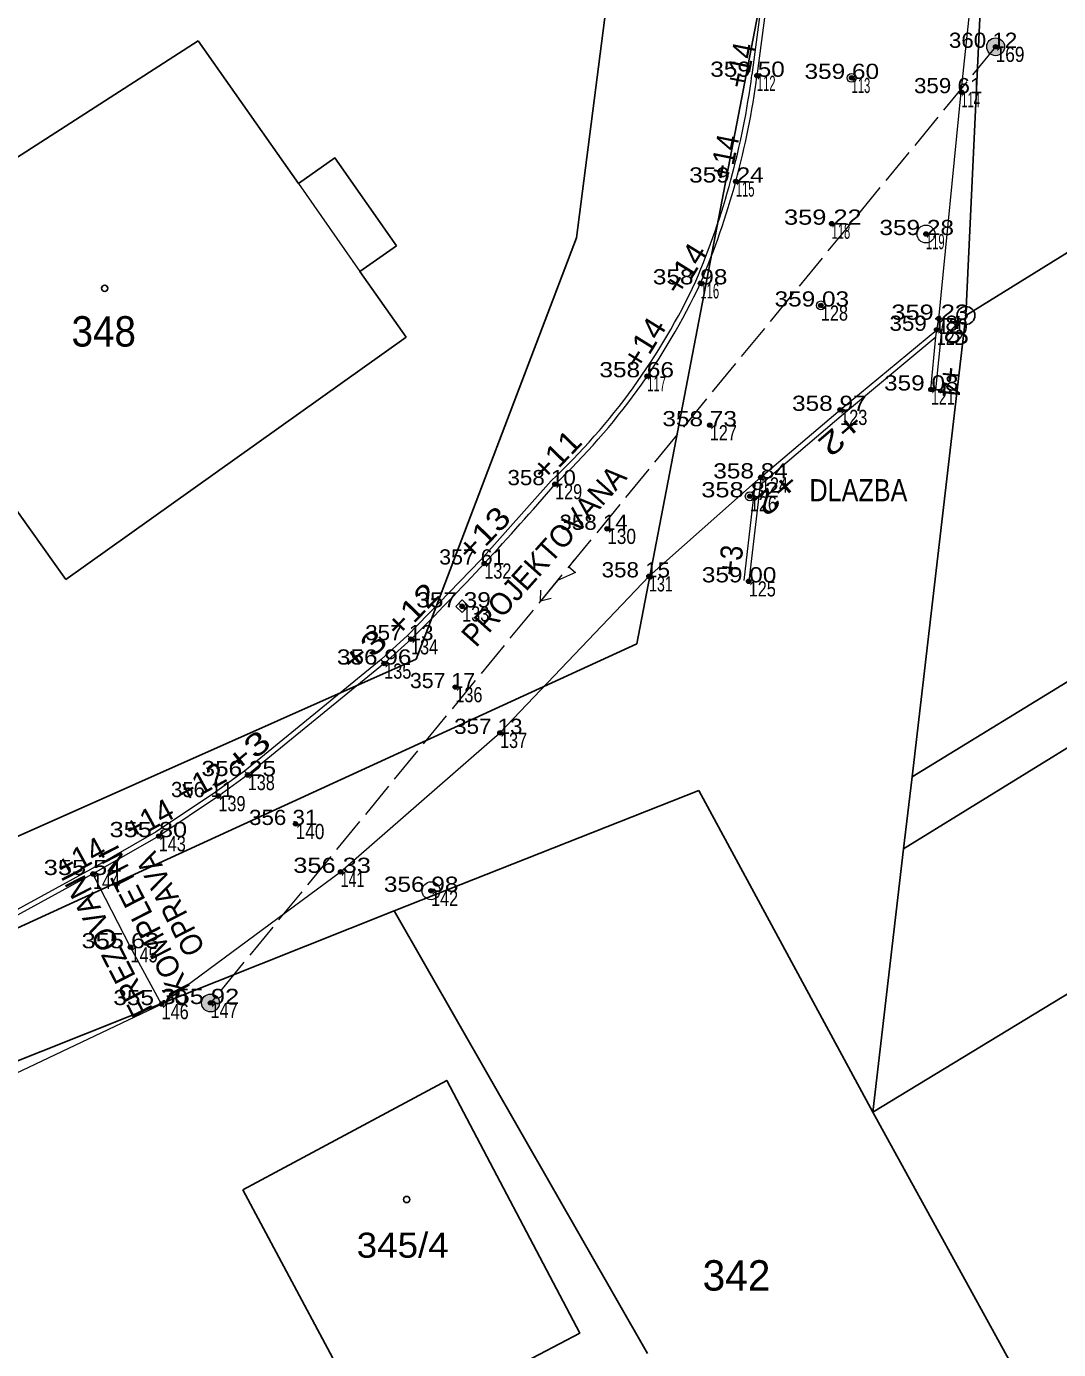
# Model space of a CAD drawing. Extents: x -592965 to -592390, y -1145071 to -1144631.
# Drawn here: x -592667.32 to -592638.44, y -1144937.57 to -1144900.54 of the extents above; entities that cross this region are included whole.
import ezdxf
from ezdxf.enums import TextEntityAlignment as Align

# ---------------------------------------------------------------- set-up
doc = ezdxf.new("R2010")
doc.units = 0
doc.header["$LTSCALE"] = 0.17
doc.header["$PDMODE"] = 32
doc.header["$PDSIZE"] = 0.085
doc.linetypes.add('LONG_DASHED', pattern=[7.5, 6, -1.5])
for name, color, linetype, lineweight in [('1', 7, 'Continuous', 13), ('3', 7, 'Continuous', 13), ('4', 7, 'Continuous', 25)]:
    doc.layers.add(name, color=color, linetype=linetype, lineweight=lineweight)
doc.layers.add('2', color=7, linetype='Continuous')

msp = doc.modelspace()

# ---------------------------------------------------------------- hatches: boundary and pattern name
at = {"layer": '1'}
for points in [[(-592639.95, -1144901.11, 1), (-592640.45, -1144901.11, 1)], [(-592661.92, -1144927.87, 1), (-592662.42, -1144927.87, 1)]]:
    msp.add_hatch(color=256, dxfattribs=at).paths.add_polyline_path(points)

# ---------------------------------------------------------------- linework, layer by layer
at = {"layer": '1', "linetype": 'LONG_DASHED'}
msp.add_line((-592640.2, -1144901.11), (-592662.17, -1144927.87), dxfattribs=at)
at = {"layer": '1'}
for p, q in [((-592641.85, -1144909.03), (-592641.79, -1144908.72)), ((-592646.93, -1144913.3), (-592647.25, -1144916.05)), ((-592655.041, -1144916.858), (-592655.219, -1144916.682)), ((-592656.56, -1144917.69), (-592656.66, -1144917.59)), ((-592657.31, -1144918.37), (-592657.4, -1144918.26)), ((-592661.13, -1144921.49), (-592661.22, -1144921.38)), ((-592661.95, -1144922.08), (-592662.03, -1144921.97))]:
    msp.add_line(p, q, dxfattribs=at)
for points in [[(-592641.79, -1144908.72), (-592641.16, -1144902.38), (-592640.38, -1144895.02), (-592640.15, -1144889.82), (-592640.65, -1144883.36), (-592641.29, -1144877.49), (-592642.3, -1144871.74), (-592643.21, -1144867.79), (-592644.53, -1144861.22), (-592645.89, -1144855.01), (-592647.22, -1144849.42), (-592648.49, -1144841.98), (-592649.04, -1144837.88), (-592648.65, -1144833.94), (-592647.63, -1144830.74), (-592645.94, -1144827.26), (-592642.72, -1144822.58), (-592638.67, -1144817.55), (-592634.67, -1144812.8), (-592632.14, -1144809.3), (-592630.54, -1144806.22), (-592629.58, -1144805.74)], [(-592647.47, -1144872.18), (-592646.45, -1144878.08), (-592646.19, -1144880.05), (-592646.12, -1144881.06), (-592646.02, -1144883.03), (-592645.98, -1144885.03), (-592645.96, -1144886.03), (-592645.96, -1144889.02), (-592646.04, -1144891.02), (-592646.42, -1144895.95), (-592646.76, -1144899.93), (-592647.02, -1144901.9)], [(-592647.33, -1144872.14), (-592646.31, -1144878.06), (-592646.05, -1144880.04), (-592645.98, -1144881.05), (-592645.88, -1144883.03), (-592645.84, -1144885.03), (-592645.82, -1144886.03), (-592645.82, -1144889.02), (-592645.9, -1144891.03), (-592646.28, -1144895.96), (-592646.62, -1144899.95), (-592646.88, -1144901.92)], [(-592646.77, -1144913.16), (-592644.55, -1144911.27), (-592641.85, -1144909.03)], [(-592642.01, -1144910.7), (-592641.87, -1144910.71), (-592641.71, -1144909.05), (-592641.65, -1144908.75), (-592641.79, -1144908.72)], [(-592642.01, -1144910.7), (-592641.87, -1144909.23), (-592641.85, -1144909.03)], [(-592646.79, -1144913.37), (-592644.46, -1144911.38), (-592641.87, -1144909.23)], [(-592652.64, -1144913.26), (-592654.61, -1144915.47), (-592656.66, -1144917.59), (-592657.4, -1144918.26), (-592661.22, -1144921.38), (-592662.03, -1144921.97), (-592663.69, -1144923.08), (-592665.53, -1144924.14), (-592669.78, -1144926.46), (-592671.54, -1144927.35), (-592674.79, -1144928.86), (-592677.96, -1144930.1), (-592680.85, -1144930.93), (-592682.8, -1144931.31), (-592683.28, -1144931.38)], [(-592682.22, -1144935.34), (-592678.43, -1144934.2), (-592676.64, -1144933.56), (-592669.86, -1144930.9), (-592663.54, -1144927.9), (-592658.53, -1144924.2), (-592654.07, -1144920.31), (-592649.9, -1144915.93), (-592646.93, -1144913.3), (-592646.77, -1144913.16)], [(-592646.77, -1144913.16), (-592646.79, -1144913.37), (-592647.11, -1144916.07)], [(-592651.99, -1144915.469), (-592652.148, -1144915.663), (-592651.955, -1144915.821), (-592652.465, -1144916.05), (-592652.94, -1144916.63)], [(-592652.637, -1144916.555), (-592652.94, -1144916.63), (-592652.927, -1144916.318)], [(-592656.56, -1144917.69), (-592657.31, -1144918.37), (-592661.13, -1144921.49), (-592661.95, -1144922.08), (-592663.62, -1144923.2), (-592665.46, -1144924.26), (-592669.71, -1144926.58), (-592671.48, -1144927.48), (-592674.74, -1144928.99), (-592677.92, -1144930.23), (-592680.82, -1144931.07), (-592682.78, -1144931.45), (-592683.26, -1144931.52)], [(-592663.54, -1144927.9), (-592664.41, -1144926.31), (-592665.46, -1144924.26)]]:
    msp.add_lwpolyline(points, dxfattribs=at)
msp.add_lwpolyline([(-592654.953, -1144916.768), (-592655.132, -1144916.593), (-592655.307, -1144916.772), (-592655.128, -1144916.947)], close=True, dxfattribs=at)
for centre, radius in [((-592640.2, -1144901.11), 0.25), ((-592644.23, -1144901.98), 0.125), ((-592642.15, -1144906.35), 0.25), ((-592645.09, -1144908.35), 0.125), ((-592647.08, -1144913.69), 0.125), ((-592656, -1144924.73), 0.25), ((-592662.17, -1144927.87), 0.25)]:
    msp.add_circle(centre, radius, dxfattribs=at)
for centre, radius, start, end in [((-592668.9952, -1144899.0192), 22.1632, 337.02545, 352.53154), ((-592668.6512, -1144899.1193), 21.9506, 336.9037, 352.66952), ((-592665.0908, -1144899.9771), 18.206, 313.14815, 335.00458), ((-592665.3788, -1144899.7612), 18.7015, 313.39658, 334.77936), ((-592708.3676, -1144865.5418), 73.5082, 314.81231, 319.42987)]:
    msp.add_arc(centre, radius, start, end, dxfattribs=at)
at = {"layer": '2'}
for p in [(-592640.2, -1144901.11), (-592646.88, -1144901.92), (-592644.23, -1144901.98), (-592641.16, -1144902.38), (-592647.47, -1144904.88), (-592644.79, -1144906.06), (-592642.15, -1144906.35), (-592648.46, -1144907.73), (-592645.09, -1144908.35), (-592641.79, -1144908.72), (-592641.85, -1144909.03), (-592649.95, -1144910.33), (-592642.01, -1144910.7), (-592644.55, -1144911.27), (-592648.2, -1144911.7), (-592646.77, -1144913.16), (-592652.53, -1144913.35), (-592647.08, -1144913.69), (-592651.07, -1144914.6), (-592654.51, -1144915.57), (-592649.9, -1144915.93), (-592647.11, -1144916.07), (-592655.13, -1144916.77), (-592656.56, -1144917.69), (-592657.31, -1144918.37), (-592655.32, -1144919.03), (-592654.07, -1144920.31), (-592661.13, -1144921.49), (-592661.95, -1144922.08), (-592659.79, -1144922.86), (-592663.62, -1144923.2), (-592665.46, -1144924.26), (-592658.53, -1144924.2), (-592656, -1144924.73), (-592664.41, -1144926.31), (-592663.54, -1144927.9), (-592662.17, -1144927.87)]:
    msp.add_point(p, dxfattribs=at)
at = {"layer": '3'}
for centre, radius in [((-592640.2001, -1144901.1099), 0.0625), ((-592640.2001, -1144901.1099), 0.0395), ((-592640.2001, -1144901.1099), 0.0125), ((-592646.8801, -1144901.9199), 0.0625), ((-592646.8801, -1144901.9199), 0.0395), ((-592646.8801, -1144901.9199), 0.0125), ((-592644.2301, -1144901.9799), 0.0625), ((-592644.2301, -1144901.9799), 0.0395), ((-592644.2301, -1144901.9799), 0.0125), ((-592641.1601, -1144902.3799), 0.0625), ((-592641.1601, -1144902.3799), 0.0395), ((-592641.1601, -1144902.3799), 0.0125), ((-592647.4701, -1144904.8799), 0.0625), ((-592647.4701, -1144904.8799), 0.0395), ((-592647.4701, -1144904.8799), 0.0125), ((-592644.7901, -1144906.0599), 0.0625), ((-592644.7901, -1144906.0599), 0.0395), ((-592644.7901, -1144906.0599), 0.0125), ((-592642.1501, -1144906.3499), 0.0625), ((-592642.1501, -1144906.3499), 0.0395), ((-592642.1501, -1144906.3499), 0.0125), ((-592648.4601, -1144907.7299), 0.0625), ((-592648.4601, -1144907.7299), 0.0395), ((-592648.4601, -1144907.7299), 0.0125), ((-592645.0901, -1144908.3499), 0.0625), ((-592645.0901, -1144908.3499), 0.0395), ((-592645.0901, -1144908.3499), 0.0125), ((-592641.7901, -1144908.7199), 0.0625), ((-592641.7901, -1144908.7199), 0.0395), ((-592641.8501, -1144909.0299), 0.0625), ((-592641.8501, -1144909.0299), 0.0395), ((-592641.8501, -1144909.0299), 0.0125), ((-592641.7901, -1144908.7199), 0.0125), ((-592649.9501, -1144910.3299), 0.0625), ((-592649.9501, -1144910.3299), 0.0395), ((-592649.9501, -1144910.3299), 0.0125), ((-592642.0101, -1144910.6999), 0.0625), ((-592642.0101, -1144910.6999), 0.0395), ((-592642.0101, -1144910.6999), 0.0125), ((-592644.5501, -1144911.2699), 0.0625), ((-592644.5501, -1144911.2699), 0.0395), ((-592644.5501, -1144911.2699), 0.0125), ((-592648.2001, -1144911.6999), 0.0625), ((-592648.2001, -1144911.6999), 0.0395), ((-592648.2001, -1144911.6999), 0.0125), ((-592646.7701, -1144913.1599), 0.0625), ((-592646.7701, -1144913.1599), 0.0395), ((-592646.7701, -1144913.1599), 0.0125), ((-592652.5301, -1144913.3499), 0.0625), ((-592652.5301, -1144913.3499), 0.0395), ((-592652.5301, -1144913.3499), 0.0125), ((-592647.0801, -1144913.6899), 0.0625), ((-592647.0801, -1144913.6899), 0.0395), ((-592647.0801, -1144913.6899), 0.0125), ((-592651.0701, -1144914.5999), 0.0625), ((-592651.0701, -1144914.5999), 0.0395), ((-592651.0701, -1144914.5999), 0.0125), ((-592654.5101, -1144915.5699), 0.0625), ((-592654.5101, -1144915.5699), 0.0395), ((-592654.5101, -1144915.5699), 0.0125), ((-592649.9001, -1144915.9299), 0.0625), ((-592649.9001, -1144915.9299), 0.0395), ((-592649.9001, -1144915.9299), 0.0125), ((-592647.1101, -1144916.0699), 0.0625), ((-592647.1101, -1144916.0699), 0.0395), ((-592647.1101, -1144916.0699), 0.0125), ((-592655.1301, -1144916.7699), 0.0625), ((-592655.1301, -1144916.7699), 0.0395), ((-592655.1301, -1144916.7699), 0.0125), ((-592656.5601, -1144917.6899), 0.0625), ((-592656.5601, -1144917.6899), 0.0395), ((-592656.5601, -1144917.6899), 0.0125), ((-592657.3101, -1144918.3699), 0.0625), ((-592657.3101, -1144918.3699), 0.0395), ((-592657.3101, -1144918.3699), 0.0125), ((-592655.3201, -1144919.0299), 0.0625), ((-592655.3201, -1144919.0299), 0.0395), ((-592655.3201, -1144919.0299), 0.0125), ((-592654.0701, -1144920.3099), 0.0625), ((-592654.0701, -1144920.3099), 0.0395), ((-592654.0701, -1144920.3099), 0.0125), ((-592661.1301, -1144921.4899), 0.0625), ((-592661.1301, -1144921.4899), 0.0395), ((-592661.1301, -1144921.4899), 0.0125), ((-592661.9501, -1144922.0799), 0.0625), ((-592661.9501, -1144922.0799), 0.0395), ((-592661.9501, -1144922.0799), 0.0125), ((-592663.6201, -1144923.1999), 0.0625), ((-592659.7901, -1144922.8599), 0.0625), ((-592659.7901, -1144922.8599), 0.0395), ((-592659.7901, -1144922.8599), 0.0125), ((-592663.6201, -1144923.1999), 0.0395), ((-592663.6201, -1144923.1999), 0.0125), ((-592665.4601, -1144924.2599), 0.0625), ((-592665.4601, -1144924.2599), 0.0395), ((-592665.4601, -1144924.2599), 0.0125), ((-592658.5301, -1144924.1999), 0.0625), ((-592658.5301, -1144924.1999), 0.0395), ((-592658.5301, -1144924.1999), 0.0125), ((-592656.0001, -1144924.7299), 0.0625), ((-592656.0001, -1144924.7299), 0.0395), ((-592656.0001, -1144924.7299), 0.0125), ((-592664.4101, -1144926.3099), 0.0625), ((-592664.4101, -1144926.3099), 0.0395), ((-592664.4101, -1144926.3099), 0.0125), ((-592663.5401, -1144927.8999), 0.0625), ((-592663.5401, -1144927.8999), 0.0395), ((-592663.5401, -1144927.8999), 0.0125), ((-592662.1701, -1144927.8699), 0.0625), ((-592662.1701, -1144927.8699), 0.0395), ((-592662.1701, -1144927.8699), 0.0125)]:
    msp.add_circle(centre, radius, dxfattribs=at)
at = {"layer": '4'}
for p, q in [((-592641.03, -1144908.63), (-592639.79, -1144882.02)), ((-592650.24, -1144917.82), (-592643.83, -1144884.47)), ((-592651.93, -1144906.46), (-592649.48, -1144887.5)), ((-592641.03, -1144908.63), (-592618.69, -1144894.73)), ((-592668.9, -1144905.05), (-592662.52, -1144900.94)), ((-592662.52, -1144900.94), (-592659.71, -1144904.94)), ((-592656.42, -1144918.25), (-592651.93, -1144906.46)), ((-592657.99, -1144907.4), (-592656.97, -1144906.68)), ((-592657.99, -1144907.4), (-592656.7, -1144909.24)), ((-592671.91, -1144908.03), (-592666.22, -1144916.02)), ((-592642.54, -1144921.54), (-592641.03, -1144908.63)), ((-592666.22, -1144916.02), (-592656.7, -1144909.24)), ((-592642.54, -1144921.54), (-592628.83, -1144913.14)), ((-592643.64, -1144930.93), (-592616.08, -1144914.18)), ((-592642.78, -1144923.56), (-592628, -1144914.45)), ((-592683.65, -1144933.15), (-592650.24, -1144917.82)), ((-592684.12, -1144930.55), (-592656.42, -1144918.25)), ((-592642.78, -1144923.56), (-592642.54, -1144921.54)), ((-592657.03, -1144925.29), (-592648.51, -1144921.92)), ((-592648.51, -1144921.92), (-592643.64, -1144930.93)), ((-592643.64, -1144930.93), (-592642.78, -1144923.56)), ((-592682.2, -1144935.31), (-592657.03, -1144925.29)), ((-592657.03, -1144925.29), (-592649.94, -1144937.68)), ((-592643.64, -1144930.93), (-592636.52, -1144943.86))]:
    msp.add_line(p, q, dxfattribs=at)
at = {"layer": '4', "lineweight": 13}
msp.add_line((-592659.71, -1144904.94), (-592657.99, -1144907.4), dxfattribs=at)
at = {"layer": '4'}
msp.add_lwpolyline([(-592659.71, -1144904.94), (-592658.69, -1144904.22), (-592656.97, -1144906.68)], dxfattribs=at)
msp.add_lwpolyline([(-592661.27, -1144933.1), (-592655.56, -1144930.04), (-592651.84, -1144937.11), (-592657.53, -1144940.1)], close=True, dxfattribs=at)
for centre, radius in [((-592665.13, -1144907.87), 0.0875), ((-592641.03, -1144908.63), 0.25), ((-592641.03, -1144908.63), 0.0164), ((-592656.68, -1144933.37), 0.0875)]:
    msp.add_circle(centre, radius, dxfattribs=at)

# ---------------------------------------------------------------- texts
at = {"layer": '1'}
for s, rotation, width, p in [('+14', 78.653, 0.9, (-592647.0434, -1144901.69)), ('+14', 78.653, 0.9, (-592647.4934, -1144904.26)), ('+14', 58.201, 1.05, (-592648.6245, -1144907.4899)), ('+6', 263.723, 0.9, (-592641.5815, -1144909.0001)), ('+14', 58.201, 1.05, (-592649.7745, -1144909.5699)), ('+4', 263.723, 0.9, (-592641.7815, -1144910.4601)), ('+2', 220.5, 1.4, (-592644.7227, -1144911.7259)), ('+11', 45.962, 1.1, (-592652.2682, -1144912.7595)), ('PROJEKTOVANA', 48.271, 0.95, (-592652.6139, -1144915.5598)), ('+2', 220.5, 1.4, (-592646.5327, -1144913.3959)), ('+13', 45.962, 1.2, (-592654.3082, -1144914.9495)), ('+3', 83.363, 0.9, (-592647.3075, -1144915.5203)), ('+12', 45.962, 1.2, (-592656.3082, -1144917.0895)), ('+3', 39.24, 1.4, (-592657.6771, -1144918.2393)), ('+3', 39.24, 1.4, (-592660.9371, -1144921.0793)), ('KOMPLETNI', 117.121, 0.95, (-592663.7565, -1144925.4173)), ('OPRAVA', 117.121, 0.9, (-592663.0167, -1144924.9678)), ('FREZOVANI', 117.121, 0.95, (-592664.7962, -1144926.0473))]:
    msp.add_text(s, height=0.62, rotation=rotation, dxfattribs=dict(at, width=width)).set_placement(p, align=Align.CENTER)
at = {"layer": '1', "width": 0.85}
msp.add_text('DLAZBA', height=0.62, dxfattribs=at).set_placement((-592644.04, -1144913.83), align=Align.CENTER)
at = {"layer": '1'}
for s, p in [('+12', (-592662.283, -1144921.9812)), ('+14', (-592663.743, -1144923.0012)), ('+14', (-592665.653, -1144924.0712))]:
    msp.add_text(s, height=0.62, rotation=28.629, dxfattribs=at).set_placement(p, align=Align.CENTER)
at = {"layer": '2'}
for s, width, p in [('169', 0.85, (-592640.2, -1144901.535)), ('112', 0.55, (-592646.88, -1144902.345)), ('113', 0.55, (-592644.23, -1144902.405)), ('114', 0.55, (-592641.16, -1144902.805)), ('115', 0.55, (-592647.47, -1144905.305)), ('118', 0.55, (-592644.79, -1144906.485)), ('119', 0.55, (-592642.15, -1144906.775)), ('116', 0.55, (-592648.46, -1144908.155)), ('128', 0.8, (-592645.09, -1144908.775)), ('122', 0.8, (-592641.85, -1144909.455)), ('120', 0.85, (-592641.79, -1144909.145)), ('117', 0.55, (-592649.95, -1144910.755)), ('121', 0.7, (-592642.01, -1144911.125)), ('123', 0.8, (-592644.55, -1144911.695)), ('127', 0.8, (-592648.2, -1144912.125)), ('129', 0.8, (-592652.53, -1144913.775)), ('124', 0.8, (-592646.77, -1144913.585)), ('126', 0.8, (-592647.08, -1144914.115)), ('130', 0.85, (-592651.07, -1144915.025)), ('132', 0.8, (-592654.51, -1144915.995)), ('131', 0.7, (-592649.9, -1144916.355)), ('125', 0.8, (-592647.11, -1144916.495)), ('133', 0.8, (-592655.13, -1144917.195)), ('134', 0.8, (-592656.56, -1144918.115)), ('135', 0.8, (-592657.31, -1144918.795)), ('136', 0.8, (-592655.32, -1144919.455)), ('137', 0.8, (-592654.07, -1144920.735)), ('138', 0.8, (-592661.13, -1144921.915)), ('139', 0.8, (-592661.95, -1144922.505)), ('140', 0.85, (-592659.79, -1144923.285)), ('143', 0.8, (-592663.62, -1144923.625)), ('141', 0.7, (-592658.53, -1144924.625)), ('144', 0.8, (-592665.46, -1144924.685)), ('142', 0.8, (-592656, -1144925.155)), ('145', 0.8, (-592664.41, -1144926.735)), ('146', 0.8, (-592663.54, -1144928.325)), ('147', 0.8, (-592662.17, -1144928.295))]:
    msp.add_text(s, height=0.425, dxfattribs=dict(at, width=width)).set_placement(p)
at = {"layer": '3'}
for s, width, p in [('360 12', 1.1, (-592640.5515, -1144901.14)), ('359 50', 1.2, (-592647.1435, -1144901.95)), ('359 60', 1.2, (-592644.505, -1144902.01)), ('359 61', 1.1, (-592641.529, -1144902.41)), ('359 24', 1.2, (-592647.7335, -1144904.91)), ('359 22', 1.25, (-592645.035, -1144906.09)), ('359 28', 1.2, (-592642.4085, -1144906.38)), ('358 98', 1.2, (-592648.7495, -1144907.76)), ('359 03', 1.2, (-592645.3435, -1144908.38)), ('359 23', 1.25, (-592642.0315, -1144908.75)), ('359 18', 1.1, (-592642.214, -1144909.06)), ('358 66', 1.2, (-592650.2445, -1144910.36)), ('359 08', 1.2, (-592642.28, -1144910.73)), ('358 97', 1.2, (-592644.8545, -1144911.3)), ('358 73', 1.2, (-592648.4825, -1144911.73)), ('358 84', 1.2, (-592647.0575, -1144913.19)), ('358 10', 1.1, (-592652.9045, -1144913.38)), ('358 82', 1.25, (-592647.3495, -1144913.72)), ('358 14', 1.1, (-592651.4515, -1144914.63)), ('357 61', 1.05, (-592654.858, -1144915.6)), ('358 15', 1.1, (-592650.2695, -1144915.96)), ('359 00', 1.2, (-592647.3785, -1144916.1)), ('357 39', 1.2, (-592655.369, -1144916.8)), ('357 13', 1.1, (-592656.886, -1144917.72)), ('356 96', 1.2, (-592657.592, -1144918.4)), ('357 17', 1.05, (-592655.678, -1144919.06)), ('357 13', 1.1, (-592654.396, -1144920.34)), ('356 25', 1.2, (-592661.3815, -1144921.52)), ('356 31', 1.1, (-592660.137, -1144922.89)), ('355 80', 1.25, (-592663.911, -1144923.23)), ('355 54', 1.25, (-592665.7525, -1144924.29)), ('356 33', 1.25, (-592658.7685, -1144924.23)), ('356 98', 1.2, (-592656.277, -1144924.76)), ('355 63', 1.25, (-592664.6925, -1144926.34)), ('355 70', 1.2, (-592663.8475, -1144927.93)), ('355 92', 1.25, (-592662.456, -1144927.9))]:
    msp.add_text(s, height=0.425, dxfattribs=dict(at, width=width)).set_placement(p, align=Align.CENTER)
msp.add_text('356 11', height=0.425, dxfattribs=at).set_placement((-592662.406, -1144922.11), align=Align.CENTER)
at = {"layer": '4'}
for s, height, width, p in [('348', 0.85, 0.95, (-592666.06, -1144909.5)), ('345/4', 0.7, 1.1, (-592658.081, -1144935))]:
    msp.add_text(s, height=height, dxfattribs=dict(at, width=width)).set_placement(p)
msp.add_text('342', height=0.85, dxfattribs=at).set_placement((-592648.4, -1144935.92))

doc.saveas('drawing.dxf')
